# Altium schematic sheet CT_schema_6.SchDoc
size 176 x 147 mm
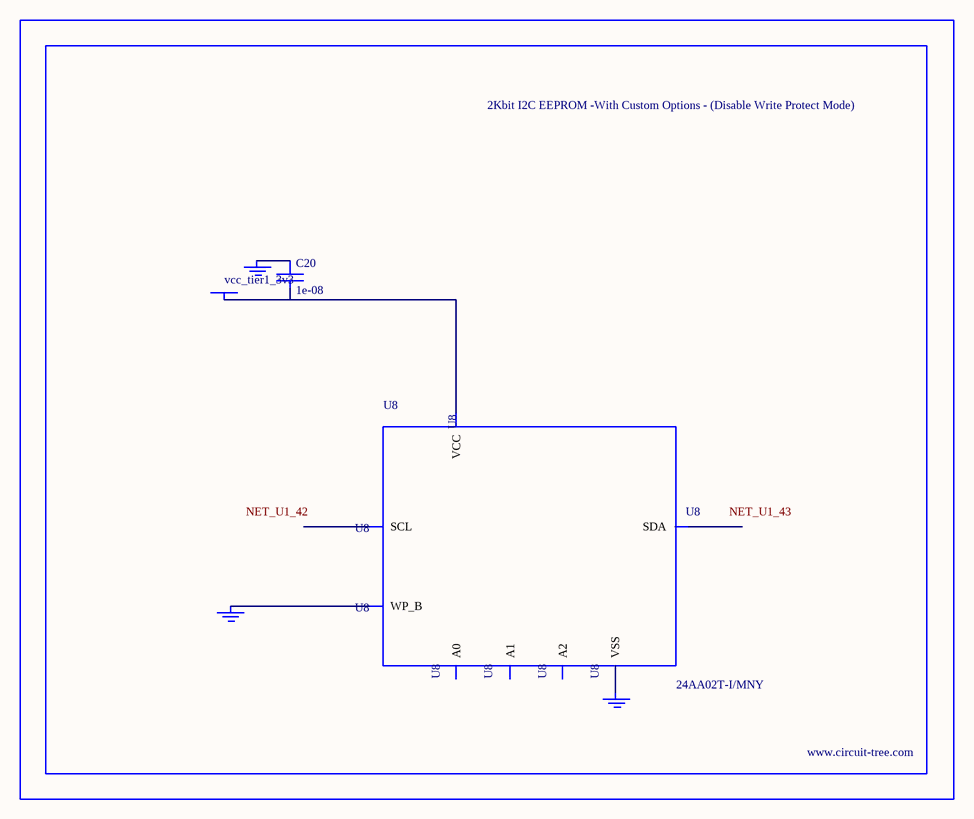
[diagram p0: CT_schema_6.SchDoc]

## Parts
BORDER5  (no value)
C20  1e-08  [C0402]
GND_INSTANCE_5_0  (no value)
GND_INSTANCE_5_1  (no value)
GND_INSTANCE_5_2  (no value)
POWER_INSTANCE_5_0  vcc_tier1_3v3
U8  24AA02T-I/MNY  [TDFN-8/6MM]

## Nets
NetC20_1: C20.1 GND_INSTANCE_5_1.0(GND)
NetC20_2: C20.2 POWER_INSTANCE_5_0.0(PWR) U8.8(VCC)
NetGND_INSTANCE_5_0_0: GND_INSTANCE_5_0.0(GND) U8.7(WP_B)
NetGND_INSTANCE_5_2_0: GND_INSTANCE_5_2.0(GND) U8.4(VSS)

Not connected (* = marked no-connect by the designer): U8 1(A0) 2(A1) 3(A2) 5(SDA) 6(SCL)

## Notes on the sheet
- Labels drawn without touching a wire or pin: NET_U1_42, NET_U1_43

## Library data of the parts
BORDER5 = BORDER_PAGE5
C20 = C0402C103K3RAC
GND_INSTANCE_5_0-GND_INSTANCE_5_2 = GND
POWER_INSTANCE_5_0 = PWR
